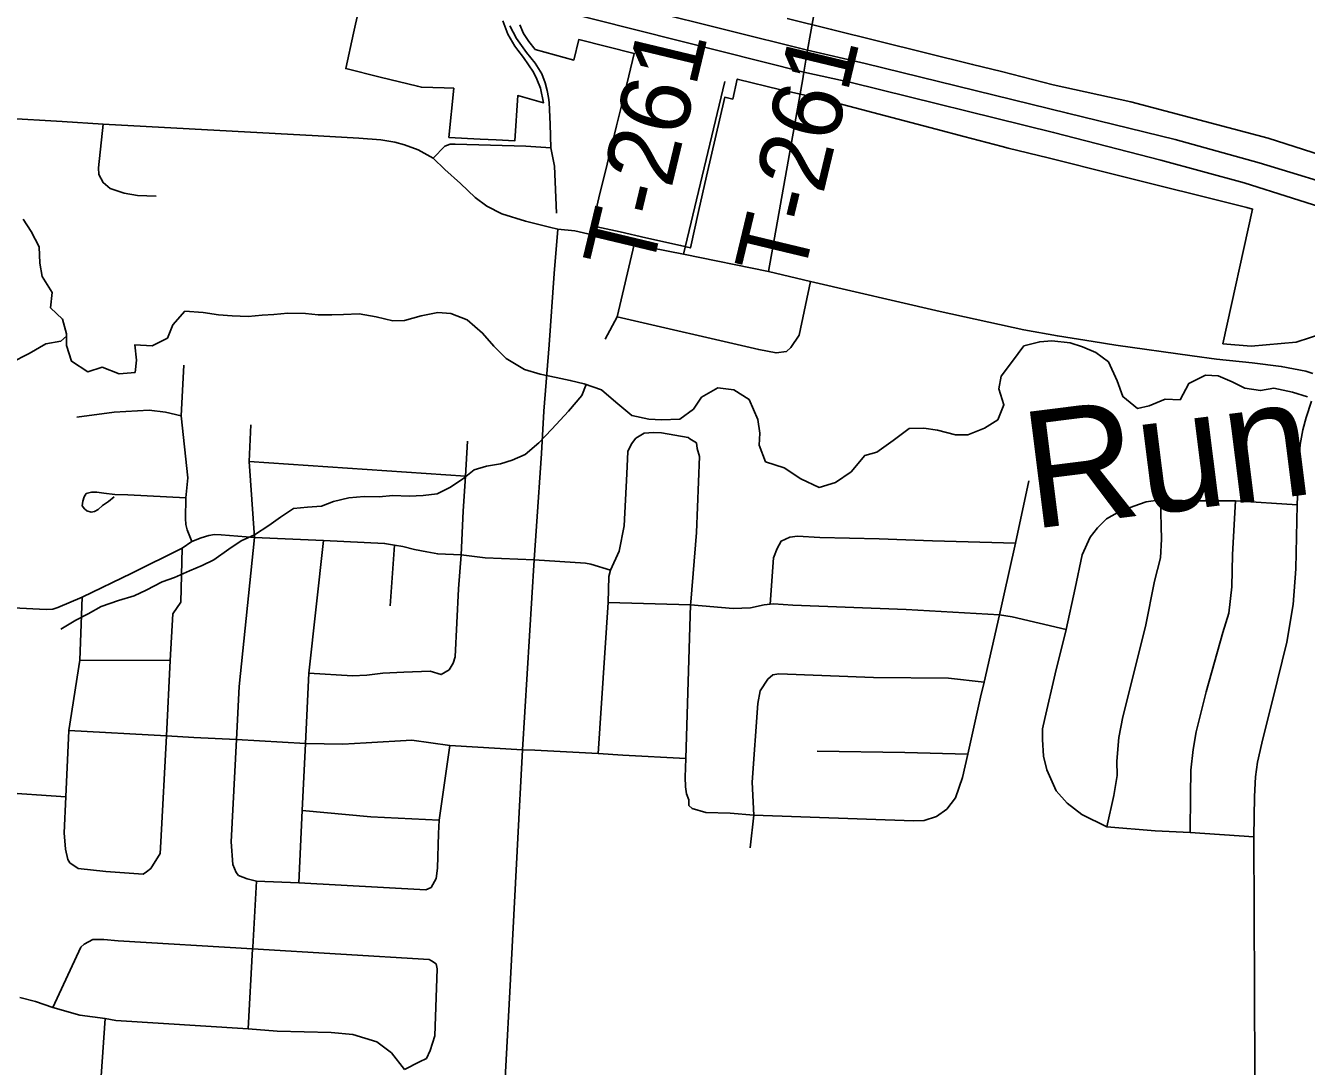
# Model space of a CAD drawing. Extents: x 114843 to 284848, y 317643 to 566895.
# Drawn here: x 184727 to 190209, y 360595 to 365050 of the extents above; entities that cross this region are included whole.
import ezdxf

# ---------------------------------------------------------------- set-up
doc = ezdxf.new("R2010")
doc.units = 0
for name, color, linetype in [('GM_X_City_Street', 7, 'Continuous'), ('GM_X_Corporation', 7, 'Continuous'), ('GM_X_County_Road', 7, 'Continuous'), ('GM_X_Interstate_Route', 7, 'Continuous'), ('GM_X_Minor_River', 7, 'Continuous'), ('GM_X_Minor_River_Text', 7, 'Continuous'), ('GM_X_Township_Road', 7, 'Continuous'), ('GM_X_Township_Road_Text', 7, 'Continuous')]:
    doc.layers.add(name, color=color, linetype=linetype)

msp = doc.modelspace()

# ---------------------------------------------------------------- linework, layer by layer
at = {"layer": 'GM_X_City_Street'}
for p, q in [((185683.5, 363184.9), (186609.5, 363121.8)), ((186287, 362566.1), (186305.5, 362825.8)), ((184958.6, 362334.6), (185346.1, 362332.1))]:
    msp.add_line(p, q, dxfattribs=at)
for points in [[(186974.7, 364527.3), (186971.6, 364628.1), (186967.4, 364721.8), (186965.2, 364742.6), (186959.9, 364772), (186951, 364805.9), (186936, 364843.9), (186908.3, 364889.4), (186871.4, 364935.3), (186827.8, 364995.9), (186799.7, 365049.1)], [(185059.4, 364629), (185038.5, 364441), (185040.6, 364412.8), (185058.8, 364378.8), (185088.9, 364352.8), (185149.2, 364333), (185205.4, 364323.2), (185285.7, 364319.6)], [(186471.1, 364483.3), (186520.8, 364534.4), (186544.7, 364543.4), (186565.6, 364543.5), (186867.4, 364534.5), (186974.7, 364527.3)], [(186999.2, 364247.4), (186990.5, 364448.9), (186974.7, 364527.3)], [(187207, 363707.7), (187258.7, 363803.1), (187332.1, 364114)], [(187258.7, 363803.1), (187865, 363663.9), (187938.8, 363649), (187983.4, 363655.1), (188002.6, 363672.7), (188037.2, 363725.3), (188086, 363954.6)], [(185438.9, 362841.8), (185418.1, 362891.9), (185413.3, 362914.2), (185410.8, 362940.4), (185412.9, 363029.4), (185421.9, 363115), (185392.7, 363380.5), (185404.7, 363597.3)], [(184946.1, 363374.3), (185106.6, 363395.1), (185255, 363403.9), (185325.2, 363396.1), (185392.7, 363380.5)], [(190266.2, 359189.8), (190133, 359418.1), (190039.9, 359614), (190012.9, 359713), (190002.3, 359773.7), (189990.5, 359869.7), (189990.2, 360185.5), (189988.5, 360562), (189986.9, 360927.4), (189983.2, 361577.2), (189986, 361750.3), (189991.5, 361835.3), (190000.1, 361898.1), (190017.8, 361978.2), (190084.7, 362248), (190125, 362411.2), (190152.2, 362572.3), (190163.2, 362725.2), (190169.3, 362998.6), (190176.1, 363180.8), (190181.6, 363256.8), (190193.3, 363319.6), (190207.1, 363372.3), (190230.9, 363442.3)], [(185637.5, 361411.8), (185627.5, 361425.8), (185613.3, 361459.9), (185606.9, 361556.2), (185629.1, 361994.1), (185640.5, 362220.9), (185706.4, 362859.8), (185683.5, 363184.9), (185690.5, 363341.6)], [(187177.1, 361934.8), (187219.6, 362580.9), (187223.1, 362692.7), (187230.3, 362718.7), (187267.2, 362800.1), (187288.2, 362908.8), (187299.6, 363132), (187305, 363226.6), (187319.5, 363260.6), (187338.4, 363284.2)], [(187338.4, 363284.2), (187374.7, 363305.3), (187414.6, 363308.6), (187448.5, 363306.7), (187562.4, 363287.9), (187570.4, 363281.9), (187598.5, 363264)], [(186539.9, 362293.1), (186557.1, 362321), (186565.6, 362348), (186579.1, 362639.8), (186591.4, 362784.6), (186599.3, 362972.4), (186609.5, 363121.8), (186618.8, 363272.1)], [(187843.2, 361670.8), (187742.9, 361678.4), (187638.5, 361681.9), (187580.3, 361699.7), (187566.2, 361711.7), (187565.7, 361736.2), (187555.1, 361761.3), (187550.6, 361791.7), (187549.4, 361833.3), (187552.3, 361913.2), (187573, 362571.1), (187573.8, 362582.6), (187598, 362880.5), (187610.8, 363205.8), (187600.6, 363239.9), (187598.5, 363264)], [(187843.2, 361670.8), (188527.3, 361645.8), (188573.4, 361648), (188625.6, 361664.3), (188669.6, 361696.6), (188707.5, 361745), (188737.3, 361831.5), (188759.7, 361931.8), (188814.2, 362175.2), (188829, 362239.7), (188895.3, 362528.6), (188912.9, 362605.3), (188963.1, 362834.7), (189021.4, 363101.8)], [(185105.8, 363032.6), (185081.3, 363013.9), (185056, 362996.4), (185037.7, 362979.3), (185021.5, 362970), (185007.7, 362967.9), (184989.2, 362973.6), (184978.3, 362982), (184969.6, 362994.9), (184971.5, 363014.3), (184977.6, 363033.6), (184986.7, 363047.1), (185009, 363053.9), (185031.7, 363053.6), (185061.4, 363048.8), (185108.1, 363043.8), (185163.9, 363041.1), (185412.9, 363029.4)], [(189180.2, 362465.1), (189219.1, 362641.6), (189248.9, 362785.2), (189283.2, 362860.5), (189315, 362900.9), (189353.6, 362938.7), (189411, 362971.3), (189469.7, 362993.1), (189523.2, 363012.3), (189584.7, 363020.7), (189722.7, 363016.4), (189904.9, 363016.4), (190169.3, 362998.6)], [(189354.6, 361619.9), (189384.8, 361754.7), (189399.1, 361840.9), (189397.4, 361902), (189405.4, 362003), (189423.3, 362091.1), (189519.6, 362477.7), (189559.1, 362672.2), (189583.8, 362771.5), (189588.6, 362852), (189584.7, 363020.7)], [(189711.2, 361596.3), (189712.5, 361755.9), (189714.3, 361863.1), (189723.6, 361951.7), (189736.7, 362027.8), (189780.4, 362198.9), (189851.4, 362451.9), (189877.5, 362535.2), (189890.1, 362647.8), (189893.2, 362785.8), (189904.9, 363016.4)], [(184673.2, 362557.8), (184814.9, 362551.1), (184843.3, 362552.6), (184865.5, 362559.5), (184969.2, 362603.6), (185180.9, 362707), (185397.1, 362813.1), (185438.9, 362841.8), (185478.9, 362857.5), (185510.4, 362867.6), (185535.1, 362871.5), (185564.1, 362871.1), (185706.4, 362859.8), (186001.3, 362846.5), (186263.5, 362833.5), (186305.5, 362825.8), (186341.4, 362820.5), (186391.6, 362807.2), (186444.2, 362797.1), (186491.2, 362788.8), (186591.4, 362784.6), (186693.6, 362772.5), (186903.1, 362764)], [(185896.4, 361380.4), (185911.1, 361690.2), (185924.8, 361977.2), (185939.1, 362278.5), (186001.3, 362846.5)], [(187913, 362573.2), (187927.4, 362771.5), (187943.2, 362811.8), (187961.2, 362844), (187997.2, 362860.2), (188031.3, 362864.4), (188125.6, 362858.8), (188380.4, 362853.9), (188609.1, 362844.9), (188963.1, 362834.7)], [(185262.3, 361442.2), (185302.2, 361506.6), (185306, 361556.8), (185329.4, 362009.7), (185346.1, 362332.1), (185356.5, 362532.9), (185390.7, 362582.5), (185397.1, 362813.1)], [(186903.1, 362764), (187123.8, 362748.9), (187146.7, 362744.7), (187230.3, 362718.7)], [(184916.1, 361466.4), (184908.1, 361480.5), (184898.3, 361524.7), (184892.6, 361595), (184899.2, 361749.5), (184912.2, 362032.6), (184958.6, 362334.6), (184969.2, 362603.6)], [(187219.6, 362580.9), (187573, 362571.1), (187755.6, 362555.9), (187829.8, 362558.2), (187888, 362570.6), (187913, 362573.2), (187928.1, 362574.8), (188010.4, 362569.1), (188495.9, 362551.2), (188895.3, 362528.6), (188949.4, 362519.1), (189180.2, 362465.1)], [(189180.2, 362465.1), (189134.1, 362276.1), (189089.5, 362084.2), (189079.8, 362040.5), (189078.9, 361994.4), (189083.2, 361923.4), (189097.3, 361864.9), (189137.9, 361774.2), (189184.4, 361722.1), (189247, 361674), (189354.6, 361619.9), (189561.6, 361603.9), (189711.2, 361596.3), (189983.2, 361577.2)], [(185939.1, 362278.5), (186125.8, 362267.4), (186188, 362269.6), (186256.2, 362278), (186346.4, 362282.4), (186458.7, 362287), (186506.2, 362272), (186539.9, 362293.1)], [(187827.7, 361530.2), (187843.2, 361670.8), (187836.6, 361811.3), (187861.5, 362148.8), (187871.3, 362203), (187903.2, 362253.4), (187925.2, 362271.5), (187951.2, 362275.7), (188356.6, 362259.5), (188677.5, 362256.9), (188829, 362239.7)], [(184912.2, 362032.6), (185329.4, 362009.7), (185446.8, 362003.2), (185629.1, 361994.1), (185924.8, 361977.2), (186084.8, 361974), (186185.1, 361980.5), (186379.6, 361991.4), (186542.2, 361969.3), (186853.2, 361950.7), (186907, 361948.5), (187177.1, 361934.8), (187283.1, 361927.8), (187552.3, 361913.2)], [(186462.2, 361361.3), (186484.1, 361399.6), (186490, 361443.8), (186493.4, 361592.4), (186496.7, 361648.8), (186542.2, 361969.3)], [(188115, 361945.1), (188490.1, 361938.8), (188759.7, 361931.8)], [(184071.3, 361865.9), (184130.6, 361816.8), (184148.6, 361800.7), (184202.8, 361796.4), (184604.8, 361769.3), (184899.2, 361749.5)], [(185911.1, 361690.2), (186204.3, 361663.3), (186496.7, 361648.8)], [(184916.1, 361466.4), (184951.3, 361442.7), (185069.8, 361429.2), (185230.3, 361417.9), (185244.3, 361428), (185262.3, 361442.2)], [(185637.5, 361411.8), (185675.7, 361397.9), (185715.5, 361388.6), (185896.4, 361380.4), (186440.2, 361351.2), (186462.2, 361361.3)], [(185679.6, 360755.9), (185698.5, 361098), (185698.9, 361104.8), (185715.5, 361388.6)], [(184843.3, 360846.5), (184962.8, 361104.9), (184976.9, 361119), (185015.1, 361138.9), (185061.3, 361138.7), (185123.5, 361132.4), (185698.5, 361098), (186454.2, 361052.8), (186464.2, 361046.7), (186484.2, 361034.6)], [(186349.1, 360581.1), (186412.1, 360615), (186442.4, 360629.3), (186458.6, 360663.4), (186478.9, 360725.5), (186488.1, 361012.5), (186484.2, 361034.6)], [(184702.3, 360890.4), (184768.5, 360872.3), (184843.3, 360846.5), (184958.9, 360814.1), (185068, 360799.6), (185113.3, 360792.1), (185679.6, 360755.9), (185803.1, 360745.8), (186034.1, 360740), (186127.3, 360732.3), (186230.1, 360700.8), (186292.5, 360653.5), (186349.1, 360581.1)], [(184932.5, 359571.6), (184976.9, 359649.7), (184993.2, 359695.8), (184995.5, 359764.1), (185023.3, 360161.8), (185068, 360799.6)]]:
    msp.add_lwpolyline(points, dxfattribs=at)
at = {"layer": 'GM_X_Corporation'}
for points in [[(186152.2, 365114.1), (186130.7, 365017.6), (186097, 364866.7), (186244, 364830.4), (186404.2, 364790.9), (186421.3, 364786.8), (186519, 364784.1), (186559.1, 364782.1), (186538.7, 364571.7), (186673, 364564.6), (186740.5, 364561), (186820.2, 364556.8), (186833.1, 364750.9), (186893.5, 364734.4), (186944, 364720.4), (186930.2, 364782.4), (186914.7, 364821), (186900.6, 364851.8), (186858.5, 364914.4), (186833.9, 364944.8), (186821.1, 364961.9), (186791, 365014.3), (186768.9, 365070.5)], [(186842, 365053.3), (186858.5, 365016.2), (186880.1, 364981.8), (186908.3, 364947.9), (187072.9, 364903.2), (187094.2, 364990.7), (187332.2, 364931.7), (187308.6, 364835.4), (187285.5, 364740.7), (187256.2, 364621.2), (187231.6, 364520.7), (187224.8, 364492.7), (187207.4, 364421.6), (187183.9, 364325.7), (187165.6, 364251.1), (187151.7, 364194), (187271.9, 364167), (187381.9, 364142.4), (187530.4, 364109.2), (187572.2, 364098.9), (187607.4, 364254.3), (187641.3, 364405.8), (187719.1, 364744.1), (187753.6, 364735.8), (187773, 364821.2), (187959.9, 364775), (188120.9, 364739.6), (188406.7, 364664.4), (188624.8, 364607.1), (188742.6, 364576.1), (188906.3, 364533.1), (188931.9, 364526.5), (189103.1, 364483.8), (189387.2, 364412.9), (189954.4, 364271.2), (189978.7, 364265), (189851.6, 363688.9), (189971.7, 363677.7), (190164.7, 363695.6), (190349.2, 363754.9)], [(190685.4, 364363.7), (190045.8, 364568.4), (189457.6, 364724.8), (189125.6, 364797.5), (188903.9, 364853.4), (188779.9, 364884.2), (188176.6, 365033.9), (187985.9, 365081)]]:
    msp.add_lwpolyline(points, dxfattribs=at)
at = {"layer": 'GM_X_County_Road'}
for points in [[(186471.1, 364483.3), (186407.4, 364518.1), (186349.1, 364540.2), (186307.4, 364551), (186246.9, 364560.8), (186153.1, 364568.9), (185979.1, 364579.2), (185059.4, 364629), (184883.1, 364639.9), (184639.1, 364654.6), (184444.5, 364672.3), (184335.9, 364682.8), (184273.1, 364712.8)], [(187004.7, 364179.4), (186969, 364187.8), (186866.4, 364214), (186765.5, 364244.6), (186701.1, 364276.8), (186650.5, 364314.3), (186588.4, 364373.9), (186521.5, 364434.3), (186471.1, 364483.3)], [(186643.7, 357875.3), (186645.2, 357916.7), (186681.1, 358602.8), (186712, 359255), (186725.7, 359516.4), (186752, 359974.1), (186767.6, 360331.7), (186799.2, 360914.9), (186840.2, 361709.3), (186845.7, 361789.2), (186853.2, 361950.7), (186903.1, 362764), (186914, 362907.8), (186934.3, 363218.8), (186944.3, 363399.4), (186967.4, 363684.3), (186989.1, 363988.7), (187004.7, 364179.4)], [(187004.7, 364179.4), (187077.6, 364171.3), (187332.1, 364114), (187542.5, 364071.6), (187907.2, 363997.9), (188086, 363954.6), (188640.7, 363827.3), (188999.4, 363748.8), (189143.3, 363721.9), (189296.5, 363697.7), (189393.7, 363682.4), (189720.2, 363637.3)], [(189720.2, 363637.3), (189823.9, 363623), (189977, 363606.8), (190100.9, 363591.7), (190206.1, 363571.2), (190235.8, 363561.5)]]:
    msp.add_lwpolyline(points, dxfattribs=at)
at = {"layer": 'GM_X_Interstate_Route'}
for points in [[(190356.2, 364246.3), (189942.5, 364377.7), (189585.6, 364474.2), (189126.5, 364593.3), (188260.7, 364806.5), (188057.9, 364850.7), (186981.8, 365122.5), (186562.9, 365224.5), (185850.4, 365391.4), (185220.8, 365545.1), (184845, 365640.4), (184796.9, 365652.1), (184403, 365748.4)], [(192417.6, 363433.4), (192329.7, 363484.1), (191976.7, 363673.9), (191668.1, 363822.4), (191390.1, 363949.6), (190919.7, 364154.8), (190419.4, 364337), (190006.5, 364463.5), (189647.7, 364563.4), (189186.2, 364674.9), (188320.5, 364888.1), (188074, 364945.2), (187041.5, 365204.1), (186622.7, 365306), (186103.9, 365439.3), (185873.6, 365490.3), (185244, 365643.9), (184940.8, 365725.6)]]:
    msp.add_lwpolyline(points, dxfattribs=at)
at = {"layer": 'GM_X_Minor_River'}
for points in [[(184717.1, 364222), (184750.8, 364169.7), (184784.4, 364103.3), (184787.9, 364033.1), (184797.6, 363976.9), (184841.1, 363908.5), (184832.7, 363842.4), (184884.4, 363794), (184902, 363731.7), (184901.7, 363681.6), (184923.3, 363613.3), (184993, 363568.8), (185055.2, 363588.4), (185127.1, 363559.9), (185195.1, 363565.5), (185201.5, 363617.6), (185193.9, 363683.8), (185267.9, 363679.3), (185334.1, 363712.9), (185356.5, 363768.9), (185408.9, 363828.7), (185486.9, 363822.2), (185552.9, 363811.8), (185610.9, 363807.4), (185678.9, 363804.9), (185739, 363810.6), (185789, 363814.3), (185849.1, 363819.9), (185925.1, 363817.4), (185979.1, 363813), (186037.1, 363812.7), (186087.1, 363814.4), (186155.2, 363815.9), (186227.1, 363803.4), (186299.1, 363786.9), (186349.1, 363788.6), (186419.3, 363808.2), (186491.4, 363821.8), (186547.4, 363817.4), (186617.3, 363790.9), (186682.9, 363734.4), (186730.6, 363677.9), (186784.3, 363625.5), (186862, 363578.9), (186929.9, 363558.4), (186997.9, 363543.9), (187057.8, 363531.5), (187117.8, 363517.1), (187191.6, 363490.6), (187253.3, 363438.1), (187321, 363381.5), (187394.9, 363365), (187448.9, 363362.6), (187527, 363366.1), (187585.3, 363407.9), (187619.6, 363459.8), (187689.9, 363499.4), (187757.9, 363490.9), (187823.7, 363450.4), (187861.1, 363364), (187868.8, 363305.8), (187866.4, 363253.7), (187894, 363183.4), (187973.9, 363156.8), (188045.6, 363110.2), (188123.4, 363073.7), (188193.6, 363095.3), (188259.9, 363140.9), (188318.4, 363210.7), (188370.5, 363224.4), (188440.8, 363274.1), (188509.2, 363325.7), (188571.2, 363327.3), (188629.2, 363319), (188707.1, 363298.4), (188759.1, 363298.1), (188831.4, 363327.7), (188887.6, 363363.4), (188914, 363427.4), (188892.5, 363495.7), (188902.8, 363549.7), (188951.2, 363613.6), (188999.7, 363679.4), (189067.8, 363697), (189119.9, 363700.7), (189197.9, 363692.1), (189249.8, 363675.8), (189307.7, 363651.3), (189361.4, 363610.9), (189398.9, 363530.5), (189422.5, 363462.2), (189486.2, 363411.6), (189536.3, 363423.4), (189604.5, 363451)], [(184902, 363721.7), (184877.8, 363699.8), (184813.7, 363688.2), (184741.4, 363646.6), (184663.1, 363607)], [(187126.1, 363514.1), (187107.4, 363467.1), (187051, 363399.3), (186978.5, 363323.6), (186924, 363263.8), (186865.7, 363214.1), (186809.5, 363190.4), (186759.4, 363174.6), (186699.3, 363165), (186647.2, 363149.3), (186596.9, 363109.5), (186542.6, 363073.8), (186488.4, 363046.1), (186428.4, 363038.5), (186368.3, 363036.8), (186298.3, 363039.3), (186240.2, 363033.6), (186176.2, 363034.1), (186110.1, 363028.5), (186044, 363012.9), (185993.9, 362993.1), (185933.8, 362989.5), (185873.7, 362983.9), (185817.5, 362946.1), (185767.2, 362910.4), (185706.9, 362870.7), (185648.8, 362845), (185596.5, 362809.3), (185532.2, 362763.6), (185482, 362739.8), (185427.8, 362716.1), (185363.6, 362688.5), (185311.5, 362668.8), (185243.2, 362633.1), (185191, 362609.4), (185124.9, 362589.8), (185050.7, 362564.2), (184994.4, 362532.5), (184942.2, 362504.8), (184878, 362467.1)], [(189604.5, 363451), (189668.5, 363448.6), (189705, 363518.5), (189777.3, 363554.1), (189831.3, 363551.7), (189891.1, 363525.3), (189945, 363498.9), (190013, 363488.4), (190069.1, 363498.1), (190149, 363481.5), (190212.9, 363461.1)]]:
    msp.add_lwpolyline(points, dxfattribs=at)
at = {"layer": 'GM_X_Township_Road'}
msp.add_line((187542.5, 364071.6), (187719.8, 364811.2), dxfattribs=at)
for points in [[(188051.7, 364814.5), (188057.9, 364850.7), (188074, 364945.2), (188099.8, 365087.6)], [(187907.2, 363997.9), (188042.1, 364757.7), (188051.7, 364814.5)]]:
    msp.add_lwpolyline(points, dxfattribs=at)

# ---------------------------------------------------------------- texts
at = {"layer": 'GM_X_Minor_River_Text'}
msp.add_text('Run', height=500, rotation=7.1698, dxfattribs=at).set_placement((189033.6, 362895))
at = {"layer": 'GM_X_Township_Road_Text'}
for rotation, p in [(76.5188, (187401.9, 363980.5)), (76.5132, (188051.5, 363955.7))]:
    msp.add_text('T-261', height=300.02, rotation=rotation, dxfattribs=at).set_placement(p)

doc.saveas('drawing.dxf')
